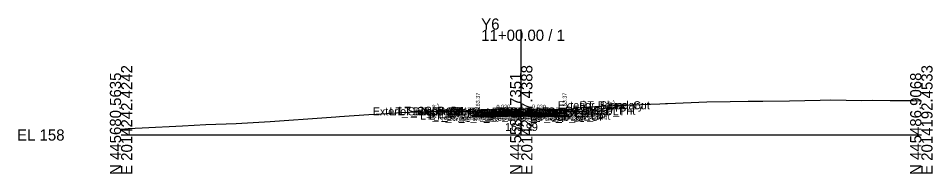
# Model space of a CAD drawing. Extents: x -26 to 203, y -10 to 4529.
# Drawn here: x -25.7 to 202.8, y 1990.3 to 2029.2 of the extents above; entities that cross this region are included whole.
import ezdxf

# ---------------------------------------------------------------- set-up
doc = ezdxf.new("R2010")
doc.units = 0
for name, color, linetype in [('Default', 7, 'Continuous'), ('Exist Cross Section Cell', 7, 'Continuous'), ('Exist XS Center Line Elevation Label', 7, 'Continuous'), ('Exist XS Ground Line', 7, 'Continuous'), ('Prop CMT Conc Surface', 7, 'Continuous'), ('Prop CMT Concrete Structures', 7, 'Continuous'), ('Prop CMT Pvmt Course 1', 7, 'Continuous'), ('Prop CMT Pvmt Course 1 CG', 7, 'Continuous'), ('Prop CMT Pvmt Course 2', 7, 'Continuous'), ('Prop CMT Pvmt Course 3', 7, 'Continuous'), ('Prop CMT Pvmt Surface', 7, 'Continuous'), ('Prop CMT Slope Grass', 7, 'Continuous'), ('Prop CMT Subgrade Earthwork', 7, 'Continuous'), ('Prop XS Earthwork Shape', 7, 'Continuous'), ('Prop XS Hydro Elevations', 7, 'Continuous'), ('Prop XS SE Text', 7, 'Continuous'), ('Prop XS Side Slope Text', 7, 'Continuous'), ('Scratch_Level_0', 7, 'Continuous')]:
    doc.layers.add(name, color=color, linetype=linetype)

msp = doc.modelspace()

# ---------------------------------------------------------------- linework, layer by layer
at = {"layer": 'Exist Cross Section Cell'}
for p, q in [((100, 2000), (100, 2026.35)), ((0, 2000), (100, 2000)), ((100, 2000), (200, 2000))]:
    msp.add_line(p, q, dxfattribs=at)
at = {"layer": 'Exist XS Ground Line'}
msp.add_lwpolyline([(0, 2001.44), (1.79, 2001.63), (5.26, 2001.78), (15.33, 2002.26), (21.21, 2002.65), (28.74, 2002.85), (37.26, 2003.34), (43.1, 2003.79), (45.47, 2003.97), (53.68, 2004.55), (54.62, 2004.62), (61.89, 2005.1), (63.76, 2005.22), (70.1, 2005.6), (74.09, 2005.81), (80.3, 2005.96), (91.58, 2005.67), (96.04, 2005.84), (100, 2005.99), (101.09, 2006.03), (105.41, 2006.05), (109.12, 2006.04), (112.94, 2006.61), (115.36, 2006.92), (123.02, 2007.36), (127.57, 2007.56), (134.68, 2007.81), (136.06, 2007.87), (136.54, 2007.87), (146.39, 2008.32), (152.2, 2008.38), (156.72, 2008.49), (160.41, 2008.47), (167.05, 2008.52), (174.71, 2008.72), (177.38, 2008.78), (185.04, 2008.66), (187.71, 2008.67), (192.23, 2008.6), (198.03, 2008.62), (200, 2008.57)], dxfattribs=at)
at = {"layer": 'Prop CMT Conc Surface'}
for points in [[(89.17, 2005.37), (89.17, 2005.87), (88.67, 2005.87)], [(91.17, 2005.49), (89.17, 2005.37)], [(108.84, 2005.49), (110.84, 2005.37)], [(110.84, 2005.37), (110.84, 2005.87), (111.34, 2005.87)]]:
    msp.add_lwpolyline(points, dxfattribs=at)
at = {"layer": 'Prop CMT Concrete Structures'}
for points in [[(91.17, 2005.49), (89.17, 2005.37), (89.17, 2005.87), (88.67, 2005.87)], [(88.67, 2005.87), (88.67, 2004.85), (91.17, 2004.9)], [(91.17, 2004.9), (91.17, 2005.49)], [(108.84, 2005.49), (110.84, 2005.37), (110.84, 2005.87), (111.34, 2005.87)], [(111.34, 2005.87), (111.34, 2004.85), (108.84, 2004.9)], [(108.84, 2004.9), (108.84, 2005.49)]]:
    msp.add_lwpolyline(points, dxfattribs=at)
at = {"layer": 'Prop CMT Pvmt Course 1'}
for points in [[(100, 2005.66), (91.17, 2005.49)], [(91.17, 2005.49), (91.17, 2005.24)], [(91.17, 2005.24), (100, 2005.41)], [(100, 2005.41), (100, 2005.66)], [(100, 2005.66), (108.84, 2005.49)], [(100, 2005.41), (100, 2005.66)], [(108.84, 2005.24), (100, 2005.41)], [(108.84, 2005.49), (108.84, 2005.24)]]:
    msp.add_lwpolyline(points, dxfattribs=at)
msp.add_lwpolyline([(100, 2005.41), (100, 2005.54), (100, 2005.54), (100, 2005.41)], close=True, dxfattribs=at)
msp.add_lwpolyline([(100, 2005.41), (100, 2005.54), (100, 2005.54), (100, 2005.41)], close=True, dxfattribs=at)
at = {"layer": 'Prop CMT Pvmt Course 1 CG'}
for points in [[(91.17, 2004.9), (88.17, 2004.84), (87.87, 2004.55)], [(87.87, 2004.55), (91.17, 2004.61)], [(91.17, 2004.61), (91.17, 2004.9)], [(108.84, 2004.9), (111.84, 2004.84), (112.13, 2004.55)], [(108.84, 2004.61), (108.84, 2004.9)], [(112.13, 2004.55), (108.84, 2004.61)]]:
    msp.add_lwpolyline(points, dxfattribs=at)
at = {"layer": 'Prop CMT Pvmt Course 2'}
for points in [[(100, 2005.41), (91.17, 2005.24)], [(91.17, 2005.24), (91.17, 2004.99)], [(91.17, 2004.99), (100, 2005.16)], [(100, 2005.16), (100, 2005.41)], [(100, 2005.16), (100, 2005.41)], [(100, 2005.41), (108.84, 2005.24)], [(108.84, 2004.99), (100, 2005.16)], [(108.84, 2005.24), (108.84, 2004.99)]]:
    msp.add_lwpolyline(points, dxfattribs=at)
at = {"layer": 'Prop CMT Pvmt Course 3'}
for points in [[(100, 2005.16), (91.17, 2004.99)], [(91.17, 2004.99), (91.17, 2004.61)], [(91.17, 2004.61), (100, 2004.79)], [(100, 2004.79), (100, 2005.16)], [(100, 2005.16), (108.84, 2004.99)], [(100, 2004.79), (100, 2005.16)], [(108.84, 2004.61), (100, 2004.79)], [(108.84, 2004.99), (108.84, 2004.61)]]:
    msp.add_lwpolyline(points, dxfattribs=at)
at = {"layer": 'Prop CMT Pvmt Surface'}
for points in [[(100, 2005.66), (91.17, 2005.49)], [(100, 2005.66), (108.84, 2005.49)]]:
    msp.add_lwpolyline(points, dxfattribs=at)
at = {"layer": 'Prop CMT Slope Grass'}
for points in [[(111.34, 2005.87), (120.84, 2006.06), (125, 2007.44)], [(88.67, 2005.87), (79.17, 2006.06), (78.77, 2005.92)]]:
    msp.add_lwpolyline(points, dxfattribs=at)
at = {"layer": 'Prop CMT Subgrade Earthwork'}
for points in [[(91.17, 2004.61), (87.87, 2004.55), (86.51, 2005.91)], [(100, 2004.79), (91.17, 2004.61)], [(100, 2004.79), (108.84, 2004.61)], [(108.84, 2004.61), (112.13, 2004.55), (113.5, 2005.91)]]:
    msp.add_lwpolyline(points, dxfattribs=at)
at = {"layer": 'Prop XS Earthwork Shape'}
for points in [[(89.17, 2005.73), (91.58, 2005.67), (96.04, 2005.84), (100, 2005.99), (101.09, 2006.03), (105.41, 2006.05), (109.12, 2006.04), (112.94, 2006.61), (115.36, 2006.92), (123.02, 2007.36), (125, 2007.44), (120.84, 2006.06), (113.5, 2005.91), (111.34, 2005.87), (110.84, 2005.87), (110.84, 2005.37), (108.84, 2005.49), (100, 2005.66), (91.17, 2005.49), (89.17, 2005.37)], [(86.51, 2005.91), (79.17, 2006.06), (78.77, 2005.92), (80.3, 2005.96), (86.62, 2005.8)], [(100, 2005.66), (91.17, 2005.49), (91.17, 2004.9), (88.67, 2004.85), (88.67, 2005.74), (86.62, 2005.8), (87.87, 2004.55), (91.17, 2004.61), (100, 2004.79), (108.84, 2004.61), (112.13, 2004.55), (113.5, 2005.91), (111.34, 2005.87), (111.34, 2004.85), (108.84, 2004.9), (108.84, 2005.49)], [(88.67, 2005.74), (88.67, 2004.85), (91.17, 2004.9), (91.17, 2005.49), (89.17, 2005.37), (89.17, 2005.73)], [(108.84, 2005.49), (110.84, 2005.37), (110.84, 2005.87), (111.34, 2005.87), (111.34, 2004.85), (108.84, 2004.9)]]:
    msp.add_lwpolyline(points, close=True, dxfattribs=at)

# ---------------------------------------------------------------- texts
at = {"layer": 'Default'}
msp.add_text('-', height=0.0001, dxfattribs=at).set_placement((0, 2000))
at = {"layer": 'Exist Cross Section Cell'}
for s, p in [('Y6', (90, 2026.35)), ('11+00.00 / 1', (90, 2023.55)), ('EL 158', (-26, 1998.6))]:
    msp.add_text(s, height=2.8, dxfattribs=at).set_placement(p)
for s, p in [('E 2014242.4242', (2.8, 1990)), ('E 2014217.4388', (102.8, 1990)), ('E 2014192.4533', (202.8, 1990)), ('N 445680.5635', (0, 1990)), ('N 445583.7351', (100, 1990)), ('N 445486.9068', (200, 1990))]:
    msp.add_text(s, height=2.8, rotation=90, dxfattribs=at).set_placement(p)
at = {"layer": 'Exist XS Center Line Elevation Label'}
msp.add_text('163.99', height=2, dxfattribs=at).set_placement((95.97, 2000.99))
at = {"layer": 'Prop XS Hydro Elevations'}
for p in [(89.67, 2006.37), (111.34, 2006.37)]:
    msp.add_text('163.37', height=1, rotation=90, dxfattribs=at).set_placement(p)
at = {"layer": 'Prop XS SE Text'}
for rotation, p in [(1.1458, (93.82, 2006.54)), (358.8542, (102.69, 2006.61))]:
    msp.add_text('0.020', height=1, rotation=rotation, dxfattribs=at).set_placement(p)
at = {"layer": 'Prop XS Side Slope Text'}
for p in [(77.98, 2006.45), (121.93, 2007.21)]:
    msp.add_text('3:1', height=1, rotation=18.4332, dxfattribs=at).set_placement(p)
at = {"layer": 'Scratch_Level_0'}
for s, p in [('Exterior Boundary', (62.91, 2004.92)), ('LT_Sub_Trench_Out_DLT', (67.08, 2004.91)), ('LT_Slope_Fill', (69.29, 2004.92)), ('LT_CSLP_Pnt', (69.34, 2005.06)), ('LT_CG_Top_Face', (76.43, 2004.87)), ('LT_CG_Top_BOC', (76.95, 2004.87)), ('LT_PV1_OEOT', (81.91, 2004.49)), ('RT_PV1_OEEOP', (89.83, 2004.54)), ('LT_PV1_OEEOP', (89.87, 2004.54)), ('RT_PV1_IEEOP', (90.47, 2004.54)), ('LT_PV1_IEEOP', (90.52, 2004.54)), ('RT_Sub_Trench_Out_DLT', (94.02, 2004.91)), ('PV1_PGL', (94.47, 2004.66)), ('RT_CG_Top_Face', (98.05, 2004.87)), ('RT_PV1_OEOT', (99.53, 2004.49)), ('RT_CG_Top_BOC', (99.57, 2004.87)), ('Exterior Boundary', (109.14, 2006.44)), ('RT_CSLP_Pnt', (110.96, 2005.06)), ('RT_Slope_Cut', (114.59, 2006.44)), ('LT_CG1_Shelf_Out', (74.72, 2003.84)), ('LT_CG_Bot_BOC', (76.99, 2003.85)), ('LT_CG_Top_Gut', (77.41, 2004.37)), ('LT_Sub_OEOP', (77.98, 2003.55)), ('LT_CG_Bot_IE', (81.08, 2003.9)), ('LT_Sub_OEOT', (81.25, 2003.61)), ('LT_PV2_OEOT', (81.34, 2004.24)), ('LT_PV3_OEOT', (81.34, 2003.99)), ('RT_Sub_OEEOP', (89.17, 2003.79)), ('LT_Sub_OEEOP', (89.21, 2003.79)), ('RT_PV2_OEEOP', (89.26, 2004.41)), ('RT_PV3_OEEOP', (89.26, 2004.16)), ('LT_PV2_OEEOP', (89.31, 2004.41)), ('LT_PV3_OEEOP', (89.31, 2004.16)), ('RT_PV2_IEEOP', (89.91, 2004.41)), ('LT_PV2_IEEOP', (89.95, 2004.41)), ('PV2_PGL', (93.91, 2004.41)), ('RT_CG1_Shelf_Out', (98.34, 2003.84)), ('RT_CG_Bot_IE', (98.7, 2003.9)), ('RT_Sub_OEOT', (98.87, 2003.61)), ('RT_PV2_OEOT', (98.96, 2004.24)), ('RT_PV3_OEOT', (98.96, 2003.99)), ('RT_CG_Top_Gut', (99.03, 2004.37)), ('RT_CG_Bot_BOC', (99.6, 2003.85)), ('RT_Sub_OEOP', (102.2, 2003.55))]:
    msp.add_text(s, height=2, dxfattribs=at).set_placement(p)

doc.saveas('drawing.dxf')
